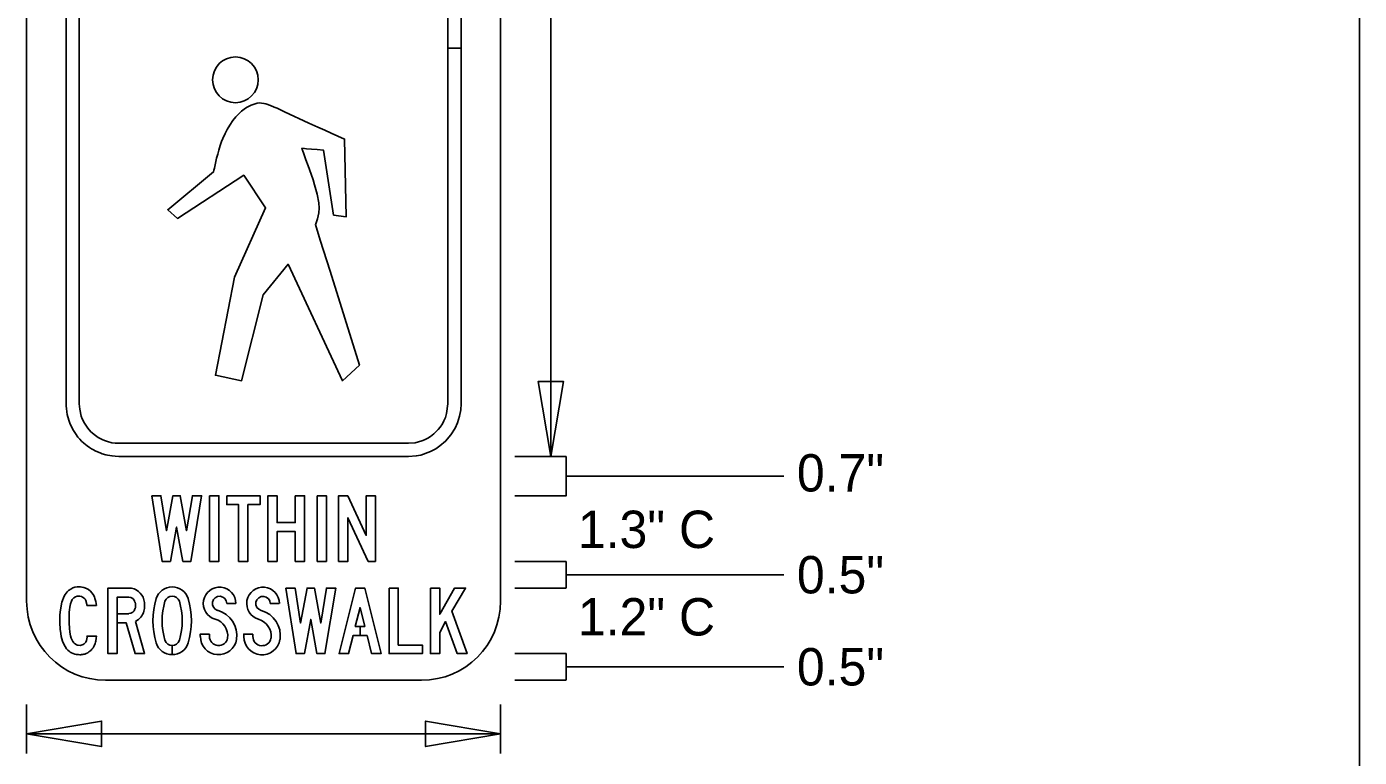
# Model space of a CAD drawing. Extents: x 0 to 770, y 0 to 495.
# Drawn here: x 260.2 to 385, y 351.1 to 419.5 of the extents above; entities that cross this region are included whole.
import ezdxf

# ---------------------------------------------------------------- set-up
doc = ezdxf.new("R2010")
doc.units = 0
for name, color, linetype in [('Default', 7, 'Continuous'), ('Dimension', 7, 'Continuous'), ('GSBWFill', 7, 'Continuous'), ('GSColorFill', 7, 'Continuous'), ('GSDims', 7, 'Continuous'), ('GSOutline', 7, 'Continuous'), ('SheetLines_dp', 7, 'Continuous'), ('TextStructures', 7, 'Continuous')]:
    doc.layers.add(name, color=color, linetype=linetype)

msp = doc.modelspace()

# ---------------------------------------------------------------- linework, layer by layer
at = {"layer": 'Default'}
for p, q in [((260.2, 484.04), (260.2, 365.71)), ((304.58, 365.71), (304.58, 484.04)), ((294.14, 366.94), (295, 366.94)), ((280.55, 362.57), (280.55, 362.63)), ((267.6, 358.31), (297.18, 358.31))]:
    msp.add_line(p, q, dxfattribs=at)
for points in [[(265.13, 463.08), (265.13, 384.2), (265.17, 383.68), (265.32, 383.04), (265.41, 382.78), (265.61, 382.39), (265.61, 382.39), (265.92, 381.92), (266.22, 381.58), (266.22, 381.58), (266.64, 381.22), (266.9, 381.04), (266.9, 381.04), (267.28, 380.84), (267.5, 380.75), (267.78, 380.65), (268.19, 380.55), (268.19, 380.55), (268.19, 380.55), (268.48, 380.52), (268.83, 380.5), (295.95, 380.5), (296.58, 380.55), (296.91, 380.63), (297.21, 380.72), (297.46, 380.82), (297.78, 380.99), (298.01, 381.13), (298.01, 381.13), (298.34, 381.38), (298.75, 381.78), (298.92, 382), (298.92, 382), (299.14, 382.32), (299.28, 382.6), (299.42, 382.92), (299.53, 383.28), (299.53, 383.28), (299.65, 384.2), (299.65, 417.5), (300.88, 417.5), (300.88, 384.2), (300.85, 383.63), (300.74, 383.05), (300.74, 383.05), (300.55, 382.42), (300.32, 381.92), (300.32, 381.92), (299.93, 381.28), (299.43, 380.71), (299.43, 380.71), (298.9, 380.25), (298.51, 379.98), (298.01, 379.72), (298.01, 379.72), (297.1, 379.4), (296.68, 379.32), (296.68, 379.32), (295.95, 379.27), (268.83, 379.27), (268.48, 379.28), (268.2, 379.31), (267.78, 379.38), (267.63, 379.42), (267.27, 379.52), (267.08, 379.59), (266.83, 379.69), (266.61, 379.8), (266.45, 379.88), (266.27, 379.98), (266.08, 380.1), (266.08, 380.1), (265.88, 380.25), (265.71, 380.38), (265.57, 380.5), (265.34, 380.71), (265.19, 380.88), (265.01, 381.08), (264.77, 381.41), (264.58, 381.71), (264.47, 381.9), (264.25, 382.37), (264.14, 382.66), (264, 383.2), (263.96, 383.43), (263.92, 383.74), (263.91, 383.97), (263.9, 384.2), (263.9, 463.08)], [(300.88, 463.08), (300.88, 417.5), (299.65, 417.5), (299.65, 463.08)], [(310.71, 379.26), (310.71, 375.57), (310.71, 377.41), (331.12, 377.41)], [(310.71, 369.42), (310.71, 366.96), (310.71, 368.19), (331.12, 368.19)], [(310.71, 360.8), (310.71, 358.34), (310.71, 359.57), (331.12, 359.57)]]:
    msp.add_lwpolyline(points, dxfattribs=at)
for points in [[(288.95, 401.86), (287.99, 407.95), (287.42, 407.99), (286.89, 408.04), (286.42, 408.08), (286.21, 408.1), (285.98, 408.12), (286.22, 407.41), (286.35, 407.04), (286.56, 406.47), (286.84, 405.7), (287.02, 405.17), (287.17, 404.69), (287.4, 403.82), (287.55, 403.01), (287.58, 402.5), (287.56, 402.09), (287.45, 401.51), (287.36, 401.23), (287.28, 401.06), (287.24, 400.97), (287.7, 399.51), (288.61, 396.6), (291.37, 387.82), (289.77, 386.35), (284.69, 397.26), (282.34, 394.39), (280.33, 386.35), (277.88, 386.87), (279.68, 396.06), (282.58, 402.54), (280.53, 405.6), (274.33, 401.55), (273.41, 402.37), (277.7, 405.91), (277.74, 406.08), (277.78, 406.25), (277.85, 406.58), (277.92, 406.89), (277.99, 407.18), (278.09, 407.58), (278.19, 407.95), (278.32, 408.39), (278.46, 408.76), (278.58, 409.04), (278.8, 409.51), (278.98, 409.87), (279.22, 410.27), (279.52, 410.72), (279.78, 411.05), (279.94, 411.23), (280.22, 411.5), (280.33, 411.6), (280.44, 411.69), (280.56, 411.78), (280.79, 411.94), (280.91, 412.01), (281.22, 412.16), (281.41, 412.23), (281.6, 412.29), (281.8, 412.34), (282.02, 412.36), (282.18, 412.35), (282.42, 412.32), (282.61, 412.27), (283.03, 412.14), (283.39, 411.98), (283.66, 411.86), (284.36, 411.53), (285.28, 411.1), (285.69, 410.91), (286.63, 410.48), (287.46, 410.11), (288.12, 409.81), (288.72, 409.54), (289.97, 408.98), (290.11, 401.69)], [(271.91, 375.58), (272.78, 375.58), (273.29, 372.3), (273.9, 375.58), (274.59, 375.58), (275.18, 372.3), (275.72, 375.58), (276.58, 375.58), (275.58, 369.44), (274.83, 369.44), (274.24, 372.65), (273.66, 369.44), (272.88, 369.44)], [(277.33, 375.58), (278.2, 375.58), (278.2, 369.44), (277.33, 369.44)], [(278.94, 375.58), (282.06, 375.58), (282.06, 374.76), (280.92, 374.76), (280.92, 369.44), (280.05, 369.44), (280.05, 374.76), (278.94, 374.76)], [(285.36, 375.58), (286.23, 375.58), (286.23, 369.44), (285.36, 369.44), (285.36, 372.23), (283.66, 372.23), (283.66, 369.44), (282.8, 369.44), (282.8, 375.58), (283.66, 375.58), (283.66, 373.08), (285.36, 373.08)], [(265.85, 365.31), (266.74, 365.31), (266.71, 365.51), (266.69, 365.67), (266.6, 365.96), (266.55, 366.12), (266.43, 366.34), (266.19, 366.64), (265.98, 366.8), (265.82, 366.89), (265.56, 367), (265.38, 367.04), (265.24, 367.06), (265.07, 367.06), (264.93, 367.05), (264.7, 367.01), (264.53, 366.95), (264.33, 366.85), (264.13, 366.71), (264, 366.6), (263.89, 366.47), (263.8, 366.34), (263.72, 366.19), (263.65, 366.04), (263.55, 365.78), (263.5, 365.62), (263.46, 365.46), (263.42, 365.25), (263.37, 364.91), (263.32, 364.42), (263.31, 364.04), (263.31, 363.68), (263.34, 363.09), (263.39, 362.68), (263.44, 362.4), (263.56, 361.98), (263.67, 361.7), (263.8, 361.46), (263.94, 361.25), (264.06, 361.12), (264.17, 361.02), (264.28, 360.95), (264.4, 360.88), (264.56, 360.8), (264.71, 360.76), (264.84, 360.73), (264.97, 360.71), (265.07, 360.71), (265.19, 360.7), (265.29, 360.7), (265.34, 360.71), (265.47, 360.72), (265.57, 360.74), (265.64, 360.76), (265.78, 360.81), (265.94, 360.89), (266.04, 360.96), (266.2, 361.09), (266.25, 361.13), (266.31, 361.21), (266.42, 361.36), (266.51, 361.52), (266.61, 361.75), (266.65, 361.89), (266.67, 361.97), (266.72, 362.24), (266.74, 362.45), (265.85, 362.45), (265.86, 362.33), (265.85, 362.2), (265.81, 362.03), (265.75, 361.89), (265.68, 361.8), (265.59, 361.72), (265.51, 361.67), (265.32, 361.59), (265.21, 361.57), (265.03, 361.58), (264.97, 361.59), (264.86, 361.63), (264.73, 361.71), (264.71, 361.72), (264.61, 361.82), (264.55, 361.9), (264.52, 361.95), (264.43, 362.12), (264.38, 362.24), (264.31, 362.47), (264.27, 362.63), (264.24, 362.85), (264.21, 363.17), (264.18, 363.68), (264.18, 364.01), (264.18, 364.23), (264.19, 364.52), (264.19, 364.67), (264.21, 364.89), (264.24, 365.15), (264.3, 365.46), (264.4, 365.73), (264.47, 365.87), (264.61, 366.02), (264.79, 366.13), (264.93, 366.17), (265.04, 366.18), (265.17, 366.18), (265.34, 366.14), (265.44, 366.1), (265.58, 366), (265.67, 365.89), (265.73, 365.78), (265.76, 365.69), (265.79, 365.6), (265.81, 365.56), (265.82, 365.5), (265.83, 365.44)], [(284.47, 366.94), (285.44, 360.8), (286.22, 360.8), (286.81, 364.01), (287.39, 360.8), (288.14, 360.8), (289.14, 366.94), (288.28, 366.94), (287.74, 363.67), (287.15, 366.94), (286.46, 366.94), (285.85, 363.67), (285.34, 366.94)], [(294.14, 366.94), (295, 366.94), (295, 361.61), (297.26, 361.61), (297.26, 360.8), (294.14, 360.8)], [(298.02, 366.94), (298.89, 366.94), (298.89, 364.49), (300.28, 366.94), (301.3, 366.94), (300.02, 364.79), (301.45, 360.8), (300.52, 360.8), (299.44, 363.8), (298.89, 362.78), (298.89, 360.8), (298.02, 360.8)]]:
    msp.add_lwpolyline(points, close=True, dxfattribs=at)
msp.add_circle((279.75, 414.53), 2.14, dxfattribs=at)
for centre, start, end in [((267.6, 365.71), 180, 270), ((297.18, 365.71), 270, 0)]:
    msp.add_arc(centre, 7.4, start, end, dxfattribs=at)
at = {"layer": 'Dimension'}
for points in [[(309.29, 379.26), (310.48, 386.27), (308.1, 386.27)], [(260.2, 353.29), (267.22, 352.1), (267.22, 354.48)], [(304.58, 353.29), (297.56, 354.48), (297.56, 352.1)]]:
    msp.add_lwpolyline(points, close=True, dxfattribs=at)
at = {"layer": 'GSBWFill'}
for p, q in [((269.78, 364.54), (269.78, 364.54)), ((278.94, 365.5), (279.8, 365.5)), ((283.01, 365.49), (283.86, 365.49)), ((277.32, 362.41), (277.32, 362.64)), ((281.39, 362.4), (281.39, 362.63)), ((273.83, 361.56), (273.83, 360.71)), ((273.83, 360.71), (273.83, 361.56))]:
    msp.add_line(p, q, dxfattribs=at)
for points in [[(287.41, 375.58), (288.27, 375.58), (288.27, 369.43), (287.41, 369.43)], [(292.19, 369.44), (292.86, 369.44), (292.86, 375.58), (292, 375.58), (292, 371.87), (290.27, 375.58), (289.42, 375.58), (289.42, 369.44), (290.28, 369.44), (290.28, 373.52)], [(291.43, 363.35), (290.98, 363.35), (291.43, 365.11), (291.87, 363.35), (291.43, 363.35), (291.43, 362.49), (292.08, 362.49), (292.51, 360.8), (293.39, 360.8), (291.86, 366.94), (291, 366.94), (289.46, 360.8), (290.35, 360.8), (290.77, 362.49), (291.43, 362.49)]]:
    msp.add_lwpolyline(points, close=True, dxfattribs=at)
for points in [[(269.78, 366.08), (268.67, 366.08), (268.67, 360.8), (267.81, 360.8), (267.81, 366.94), (269.78, 366.94)], [(270.39, 363.82), (271.25, 360.8), (270.35, 360.8), (269.53, 363.68), (268.67, 363.68), (268.67, 364.54), (269.78, 364.54)], [(277.32, 362.64), (276.46, 362.64), (276.46, 362.41)], [(281.39, 362.63), (280.53, 362.63), (280.53, 362.4)]]:
    msp.add_lwpolyline(points, dxfattribs=at)
for centre, radius, start, end in [((269.78, 365.5), 1.44, 13.8865, 90), ((273.83, 365.49), 1.56, 17.3283, 162.6717), ((278.27, 365.5), 1.53, 0, 254.2259), ((282.34, 365.49), 1.53, 0, 254.2259), ((269.78, 365.5), 0.583, 13.8865, 90), ((269.04, 365.31), 2.21, 346.1135, 13.8865), ((278.99, 363.88), 6.97, 162.6717, 197.3283), ((278.99, 363.88), 6.11, 162.6717, 197.3283), ((273.83, 365.49), 0.705, 17.3283, 162.6717), ((268.67, 363.88), 6.11, 342.6717, 17.3283), ((268.67, 363.88), 6.97, 342.6717, 17.3283), ((278.27, 365.5), 0.673, 0, 254.2259), ((282.34, 365.49), 0.673, 0, 254.2259), ((269.78, 365.13), 0.583, 270, 346.1135), ((269.04, 365.31), 1.35, 346.1135, 13.8865), ((269.78, 365.13), 1.44, 294.8221, 346.1135), ((277.41, 362.47), 2.48, 352.1298, 74.2259), ((281.48, 362.46), 2.48, 352.1298, 74.2259), ((277.41, 362.47), 1.62, 352.5804, 74.2259), ((281.48, 362.46), 1.62, 352.5804, 74.2259), ((273.83, 362.27), 0.705, 197.3283, 270), ((273.83, 362.27), 0.705, 270.0249, 342.6717), ((278.18, 362.41), 1.71, 180, 350.5313), ((278.18, 362.41), 0.856, 180, 349.7857), ((282.24, 362.4), 1.71, 180, 350.5313), ((282.24, 362.4), 0.856, 180, 349.7857), ((273.83, 362.27), 1.56, 197.3283, 270), ((273.83, 362.27), 1.56, 270.0112, 342.6717)]:
    msp.add_arc(centre, radius, start, end, dxfattribs=at)
at = {"layer": 'GSColorFill'}
for p, q in [((269.78, 364.54), (269.78, 364.54)), ((278.94, 365.5), (279.8, 365.5)), ((283.01, 365.49), (283.86, 365.49)), ((277.32, 362.41), (277.32, 362.64)), ((281.39, 362.4), (281.39, 362.63)), ((273.83, 361.56), (273.83, 360.71)), ((273.83, 360.71), (273.83, 361.56))]:
    msp.add_line(p, q, dxfattribs=at)
for points in [[(287.41, 375.58), (288.27, 375.58), (288.27, 369.43), (287.41, 369.43)], [(292.19, 369.44), (292.86, 369.44), (292.86, 375.58), (292, 375.58), (292, 371.87), (290.27, 375.58), (289.42, 375.58), (289.42, 369.44), (290.28, 369.44), (290.28, 373.52)], [(291.43, 363.35), (290.98, 363.35), (291.43, 365.11), (291.87, 363.35), (291.43, 363.35), (291.43, 362.49), (292.08, 362.49), (292.51, 360.8), (293.39, 360.8), (291.86, 366.94), (291, 366.94), (289.46, 360.8), (290.35, 360.8), (290.77, 362.49), (291.43, 362.49)]]:
    msp.add_lwpolyline(points, close=True, dxfattribs=at)
for points in [[(269.78, 366.08), (268.67, 366.08), (268.67, 360.8), (267.81, 360.8), (267.81, 366.94), (269.78, 366.94)], [(270.39, 363.82), (271.25, 360.8), (270.35, 360.8), (269.53, 363.68), (268.67, 363.68), (268.67, 364.54), (269.78, 364.54)], [(277.32, 362.64), (276.46, 362.64), (276.46, 362.41)], [(281.39, 362.63), (280.53, 362.63), (280.53, 362.4)]]:
    msp.add_lwpolyline(points, dxfattribs=at)
for centre, radius, start, end in [((269.78, 365.5), 1.44, 13.8865, 90), ((273.83, 365.49), 1.56, 17.3283, 162.6717), ((278.27, 365.5), 1.53, 0, 254.2259), ((282.34, 365.49), 1.53, 0, 254.2259), ((269.78, 365.5), 0.583, 13.8865, 90), ((269.04, 365.31), 2.21, 346.1135, 13.8865), ((278.99, 363.88), 6.97, 162.6717, 197.3283), ((278.99, 363.88), 6.11, 162.6717, 197.3283), ((273.83, 365.49), 0.705, 17.3283, 162.6717), ((268.67, 363.88), 6.11, 342.6717, 17.3283), ((268.67, 363.88), 6.97, 342.6717, 17.3283), ((278.27, 365.5), 0.673, 0, 254.2259), ((282.34, 365.49), 0.673, 0, 254.2259), ((269.78, 365.13), 0.583, 270, 346.1135), ((269.04, 365.31), 1.35, 346.1135, 13.8865), ((269.78, 365.13), 1.44, 294.8221, 346.1135), ((277.41, 362.47), 2.48, 352.1298, 74.2259), ((281.48, 362.46), 2.48, 352.1298, 74.2259), ((277.41, 362.47), 1.62, 352.5804, 74.2259), ((281.48, 362.46), 1.62, 352.5804, 74.2259), ((273.83, 362.27), 0.705, 197.3283, 270), ((273.83, 362.27), 0.705, 270.0249, 342.6717), ((278.18, 362.41), 1.71, 180, 350.5313), ((278.18, 362.41), 0.856, 180, 349.7857), ((282.24, 362.4), 1.71, 180, 350.5313), ((282.24, 362.4), 0.856, 180, 349.7857), ((273.83, 362.27), 1.56, 197.3283, 270), ((273.83, 362.27), 1.56, 270.0112, 342.6717)]:
    msp.add_arc(centre, radius, start, end, dxfattribs=at)
at = {"layer": 'GSDims'}
for p, q in [((309.29, 379.26), (309.29, 468)), ((305.91, 379.26), (310.71, 379.26)), ((305.91, 375.57), (310.71, 375.57)), ((305.91, 369.42), (310.71, 369.42)), ((305.91, 366.94), (310.71, 366.94)), ((305.91, 360.8), (310.71, 360.8)), ((305.91, 358.31), (310.71, 358.31)), ((260.2, 356.05), (260.2, 351.45)), ((304.58, 356.05), (304.58, 351.45)), ((260.2, 353.29), (304.58, 353.29))]:
    msp.add_line(p, q, dxfattribs=at)
at = {"layer": 'GSOutline'}
for p, q in [((269.78, 366.94), (267.81, 366.94)), ((269.78, 366.08), (269.78, 366.08)), ((278.94, 365.5), (279.8, 365.5)), ((283.01, 365.49), (283.86, 365.49)), ((277.32, 362.41), (277.32, 362.64)), ((281.39, 362.4), (281.39, 362.63))]:
    msp.add_line(p, q, dxfattribs=at)
for points in [[(287.41, 375.58), (288.27, 375.58), (288.27, 369.43), (287.41, 369.43)], [(292.19, 369.44), (292.86, 369.44), (292.86, 375.58), (292, 375.58), (292, 371.87), (290.27, 375.58), (289.42, 375.58), (289.42, 369.44), (290.28, 369.44), (290.28, 373.52)], [(290.77, 362.49), (292.08, 362.49), (292.51, 360.8), (293.39, 360.8), (291.86, 366.94), (291, 366.94), (289.46, 360.8), (290.35, 360.8)], [(291.87, 363.35), (291.43, 365.11), (290.98, 363.35)]]:
    msp.add_lwpolyline(points, close=True, dxfattribs=at)
for points in [[(267.81, 366.94), (267.81, 360.8), (268.67, 360.8), (268.67, 363.68), (269.53, 363.68), (270.35, 360.8), (271.25, 360.8), (270.39, 363.82)], [(269.78, 366.08), (268.67, 366.08), (268.67, 364.54), (269.78, 364.54)], [(277.32, 362.64), (276.46, 362.64), (276.46, 362.41)], [(281.39, 362.63), (280.53, 362.63), (280.53, 362.4)]]:
    msp.add_lwpolyline(points, dxfattribs=at)
for centre, radius, start, end in [((269.78, 365.5), 1.44, 13.8865, 90), ((273.83, 365.49), 1.56, 17.3283, 162.6717), ((278.27, 365.5), 1.53, 0, 254.2259), ((282.34, 365.49), 1.53, 0, 254.2259), ((269.78, 365.5), 0.583, 13.8865, 90), ((269.04, 365.31), 2.21, 346.1135, 13.8865), ((278.99, 363.88), 6.97, 162.6717, 197.3283), ((278.99, 363.88), 6.11, 162.6717, 197.3283), ((273.83, 365.49), 0.705, 17.3283, 162.6717), ((268.67, 363.88), 6.11, 342.6717, 17.3283), ((268.67, 363.88), 6.97, 342.6717, 17.3283), ((278.27, 365.5), 0.673, 0, 254.2259), ((282.34, 365.49), 0.673, 0, 254.2259), ((269.78, 365.13), 0.583, 270, 346.1135), ((269.04, 365.31), 1.35, 346.1135, 13.8865), ((269.78, 365.13), 1.44, 294.8221, 346.1135), ((277.41, 362.47), 2.48, 352.1298, 74.2259), ((281.48, 362.46), 2.48, 352.1298, 74.2259), ((277.41, 362.47), 1.62, 352.5804, 74.2259), ((281.48, 362.46), 1.62, 352.5804, 74.2259), ((273.83, 362.27), 0.705, 197.3283, 342.6717), ((278.18, 362.41), 1.71, 180, 350.5313), ((278.18, 362.41), 0.856, 180, 349.7857), ((282.24, 362.4), 1.71, 180, 350.5313), ((282.24, 362.4), 0.856, 180, 349.7857), ((273.83, 362.27), 1.56, 197.3283, 342.6717)]:
    msp.add_arc(centre, radius, start, end, dxfattribs=at)
at = {"layer": 'SheetLines_dp'}
msp.add_line((385, 0), (385, 495), dxfattribs=at)

# ---------------------------------------------------------------- texts
at = {"layer": 'TextStructures'}
for s, p in [('0.7"', (332.33, 375.98)), ('1.3" C', (311.82, 370.69)), ('0.5"', (332.33, 366.44)), ('1.2" C', (311.82, 362.5)), ('0.5"', (332.33, 357.82))]:
    msp.add_text(s, height=3.5, dxfattribs=at).set_placement(p)

doc.saveas('drawing.dxf')
